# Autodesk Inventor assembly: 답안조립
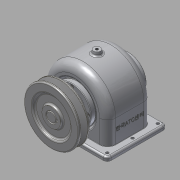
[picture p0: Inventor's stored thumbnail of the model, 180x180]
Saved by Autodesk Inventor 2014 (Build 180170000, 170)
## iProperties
Created: 2015-09
Part Number: 답안조립
Document SubType Name: Assembly
Designer: Owner
Mass: 2342.49 g
Surface Area: 1861.77 cm^2
Volume: 494.075 cm^3
Density: 4.74116 g/cm^3
Author: Owner
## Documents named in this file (14)
- C:\Documents and Settings\Owner\바탕 화면\450907V1026\답안조립.iam
- C:\Documents and Settings\Owner\바탕 화면\450907V1026\본체.ipt
- C:\Documents and Settings\Owner\바탕 화면\450907V1026\V-벨트풀리.ipt
- C:\Documents and Settings\Owner\바탕 화면\450907V1026\뒤커버.ipt
- C:\Documents and Settings\Owner\바탕 화면\450907V1026\멈춤나사 - M4x10.ipt
- C:\Documents and Settings\Owner\바탕 화면\450907V1026\베어링 6203.ipt
- C:\Documents and Settings\Owner\바탕 화면\450907V1026\볼트 M3 x 8.ipt
- C:\Documents and Settings\Owner\바탕 화면\450907V1026\볼트 M3 x 10.ipt
- C:\Documents and Settings\Owner\바탕 화면\450907V1026\스퍼기어.ipt
- C:\Documents and Settings\Owner\바탕 화면\450907V1026\앞커버.ipt
- C:\Documents and Settings\Owner\바탕 화면\450907V1026\오일 실 17 32 8.ipt
- C:\Documents and Settings\Owner\바탕 화면\450907V1026\축.ipt
- C:\Documents and Settings\Owner\바탕 화면\450907V1026\키 - 5 x 5 x 18.ipt
- C:\Documents and Settings\Owner\바탕 화면\450907V1026\키 - 6 x 6 x 22.ipt
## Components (9 placed, 3 different names)
1. V-벨트풀리:1 — 플러쉬:1
2. ISO 4762 M3 x 8:1
3. ISO 4762 M3 x 8:2
4. ISO 4762 M3 x 8:3
5. ISO 4762 M3 x 8:4
6. ISO 4762 M3 x 10:1
7. ISO 4762 M3 x 10:2
8. ISO 4762 M3 x 10:3
9. ISO 4762 M3 x 10:4
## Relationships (1: Flush 1)
- 플러쉬:1 [Flush]: V-벨트풀리:1
